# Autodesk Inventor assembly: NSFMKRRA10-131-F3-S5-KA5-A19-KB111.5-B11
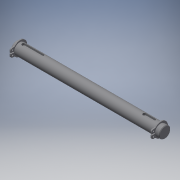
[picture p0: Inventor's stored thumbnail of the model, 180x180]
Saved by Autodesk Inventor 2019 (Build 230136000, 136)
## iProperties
Category: PARTsolutions
Company: MISUMI
Created: 2022-11
Part Number: NSFMKRRA10-131-F3-S5-KA5-A19-KB111.5-B11
Catalog Web Link: www.cadenas.de
Description: NSFMKRR, SFMKRR, PSFMKRR, SSFMKRR, NSFHKRR, SFHKRR, PSFHKRR, SSFHKRR, NSFGKRR, SFGKRR, PSFGKRR, SSFGKRR, NSFMKRRA, SFMKRRA, PSFMKRRA, SSFMKRRA, NSFHKRRA, SFHKRR
Vendor: MISUMI
Document SubType Name: Assembly
Designer: psAdmin
Manufacturer: MISUMI
Mass: 10.2368 g
Surface Area: 47.8895 cm^2
Volume: 10.2368 cm^3
Density: 1 g/cm^3
Title: NSFMKRRA10-131-F3-S5-KA5-A19-KB111.5-B11
Author: Cadenas PARTsolutions
Comments: Rotary Shafts - Retaining Ring Grooves on Both Ends with Keyway -
PSOL_IDENT_0: {$CADENAS_DATA/23d-libs/misumi/metric/11_rotary_shafts/psfgkrr_asmtab.prj},644 {VTYP=3D},{STYP=ASSTA
PSOL_IDENT_1: B},{NB=NSFMKRRA10-131-F3-S5-KA5-A19-KB111.5-B11},{LINA=NSFMKRRA10-131-F3-S5-KA5-A19-KB111.5-B11},{NN=
PSOL_IDENT_2: NSFMKRR, SFMKRR, PSFMKRR, SSFMKRR, NSFHKRR, SFHKRR, PSFHKRR, SSFHKRR, NSFGKRR, SFGKRR, PSFGKRR, SSFG
PSOL_IDENT_3: KRR, NSFMKRRA, SFMKRRA, PSFMKRRA, SSFMKRRA, NSFHKRRA, SFHKRRA, PSFHKRRA, SSFHKRRA, NSFGKRRA, SFGKRRA
PSOL_IDENT_4: , PSFGKRRA, SSFGKRRA},{DATE=25.01.2022 23:09:58},{GEOMDATE=05.02.2021 08:16:43},{VERSION=},{LINEID=3
PSOL_IDENT_5: 0},{WBVAR=TS,TYS,MAT,ST,ALT1,L,F,S,NOK,KA,A,KB,B,KC,C,ALT3,FC,GALT3,WFC,J,WALT3,V,ALT4,SFC,SG,AG,ALT
PSOL_IDENT_6: 10,KWC,ALT11,WC,ALT5,UC,ALT7,SC,ALT32,CD},{WBNUMERIC=L,F,S,KA,A,KB,B,KC,C,FC,GALT3,WFC,J,WALT3,V,SFC
PSOL_IDENT_7: ,SG,AG,KWC,WC,UC,SC}  {NB=NSFMKRRA10-131-F3-S5-KA5-A19-KB111.5-B11},{LINA=NSFMKRRA10-131-F3-S5-KA5-A
PSOL_IDENT_8: 19-KB111.5-B11},{KT=DUMMY},{PN=NSFMKRRA10-131-F3-S5-KA5-A19-KB111.5-B11},{TS=A},{TSALG='','Standard'
PSOL_IDENT_9: ,'A','Retaining Ring'},{TYS=M},{TYSALG= 'M','h9 (Cold-drawn)','H','h7 (Ground)','G','g6 (Ground)' },
PSOL_IDENT_10: {MAT=S45C},{MATALG= 'S45C','S45C Equivalent', 'SUS304','304 Stainless Steel' },{ST=},{STALG= '','-','
PSOL_IDENT_11: BO','Black Oxide', 'ENP','Electroless Nickel Plating' },{TYPE=NSFMKRR},{D=10},{ALT1=},{LKCMAX=799.9}
PSOL_IDENT_12: ,{L=131.0},{LALG=[15:800/0.1]},{LMIN=15},{LMAX=800},{F=3.0},{FALG=[3:126/0.1]},{FMIN=3},{FMAX1=122.8
PSOL_IDENT_13: },{FMIN2=6.2},{FMAX2=126},{S=5.0},{SALG=[3:126/0.1]},{SMIN1=3},{SMAX1=121},{SMIN2=6.2},{SMAX2=126},{
PSOL_IDENT_14: DD=9.6},{MM=1.15},{MMALG=1.2},{MMJ=2},{NOK=2},{NOKALG= '1', 'with 1 Key Groove', '2'  , 'with 2 Key
PSOL_IDENT_15: Grooves', '3'  , 'with 3 Key Grooves'},{CIFNOK1=0},{CIFNOK2=3},{CIFNOK3=0},{TOL1=0},{TOL2=3},{TOL3=0
PSOL_IDENT_16: },{BB=3},{TT=1.8},{KA=5.0},{KAALG=[5:116/0.1]},{KAMIN1=0},{KAMIN2=5},{KAMIN3=129.2},{KAMAX1=-1000},{
PSOL_IDENT_17: KAMAX2=116},{KAMAX3=-1000},{A=19.0},{AALG=[3:100/0.1]},{AMIN=3},{AMAX=100},{AMAX1=-1000},{AMAX2=100}
PSOL_IDENT_18: ,{AMAX3=-1000},{KAPN=-KA5-A19},{KB=111.5},{KBALG=[26:121/0.1]},{KBMIN1=26},{KBMIN2=26},{KBMIN3=129.2
PSOL_IDENT_19: },{KBMAX1=-1000},{KBMAX2=121},{KBMAX3=-1000},{B=11.0},{BALG=[3:12.5/0.1]},{BMIN=3},{BMAX=12.5},{BMAX
PSOL_IDENT_20: 1=-1000},{BMAX2=12.5},{BMAX3=-1000},{KBPN=-KB111.5-B11},{KC=0.0},{KCALG=[0]},{KCMIN1=124.5},{KCMIN2=
PSOL_IDENT_21: 124.5},{KCMIN3=129.2},{KCMAX1=-1000},{KCMAX2=-1000},{KCMAX3=-1000},{C=0.0},{CALG=0},{CMIN=3},{CMAX=-
PSOL_IDENT_22: 1000},{CMAX1=-1000},{CMAX2=-1000},{CMAX3=-1000},{CIFKA=5},{CIFKB=3},{CIFKC=3},{KCPN=},{ALT3=},{ALT3A
PSOL_IDENT_23: LG= '', 'w/o Set Screw Flat','FC','with FC (Adds a Set Screw Flat)','WFC','with WFC (Adds Two Set Sc
PSOL_IDENT_24: rew Flats)','FCWFC','with FC + WFC (Adds Three Set Screw Flats)' },{ALT3PN=},{FC=0},{FCALG=[0]},{FCM
PSOL_IDENT_25: IN=0},{FCMAX=130},{GALT3=0},{GALT3ALG=[0]},{GALT3MIN=1},{GALT3MAX=70},{GALT3MAX2=70},{GALT3MAX3=70},
PSOL_IDENT_26: {WFC=0},{WFCALG=[0]},{WFCMIN=0},{WFCMIN2=2},{WFCMAX=127},{WFCMAX2=-3},{WFCMAX3=-4},{J=0},{JALG=[0]},
PSOL_IDENT_27: {JMIN=1},{JMAX=70},{JMAX2=-2},{JMAX3=-5},{WALT3=0},{WALT3ALG=[0]},{WALT3MIN=0},{WALT3MIN2=133},{WALT
PSOL_IDENT_28: 3MAX=128},{WALT3MAX2=128},{V=0},{VALG=[0]},{VMIN=1},{VMAX=70},{VMAX2=70},{CIFFC=0},{ALT4=},{ALT4ALG=
PSOL_IDENT_29: '', 'w/o SFC (2 Set Screw Flats (Angle Specified))', 'SFC'  , 'with SFC (2 Set Screw Flats (Angle S
PSOL_IDENT_30: pecified))'},{ALT4PN=},{SFC=0},{SFCALG=[0]},{SFCMIN=0},{SFCMAX=130},{SG=0},{SGALG=[0]},{SGMIN=1},{SG
PSOL_IDENT_31: MAX=70},{AG=0},{AGALG=[0]},{H=0},{CIFSFC=0},{ALT10=},{ALT10ALG= '','Not applicable' },{KWC=0},{KWCAL
PSOL_IDENT_32: G=[0]},{KWCMIN=1},{KWCMAX=0},{WALT10=8},{ALT10PN=},{ALT11=},{ALT11ALG= '','Not applicable' },{WC=0.0
PSOL_IDENT_33: },{WCALG=[0]},{ALT11PN=},{ALT5=},{ALT5ALG= '', 'w/o UC (Slit Cam Groove)', 'UC', 'with UC (Slit Cam
PSOL_IDENT_34: Groove)'},{ALT5PN=},{UC=0},{UCALG=[0]},{UCMIN=1},{UCMAX=125},{DDALT5=0},{LL1=0},{ALT7=},{ALT7ALG= ''
PSOL_IDENT_35: , 'w/o SC (Wrench Flats)', 'SC', 'with SC (Wrench Flats)'},{ALT7PN=},{SC=0},{SCALG=[0]},{SCMIN=0},{S
PSOL_IDENT_36: CMAX=123},{LL2=0},{LL2ALG=8},{WALT7=0},{CIFSC=0},{ALT32=},{ALT32ALG= '','w/o CD (Changes Part D Cham
PSOL_IDENT_37: fering)','CD','with CD (Changes Part D Chamfering)' },{CD=},{CDALG= '','N/A' },{CD3D=0.5},{ALT32PN=}
PSOL_IDENT_38: ,{CIF323R=0},{CIF323L=0},{CIF324R=0},{CIF324L=0},{CIF3210=0},{CIF32F=0},{CIF32S=0},{ERRORPN=},{ERROR
PSOL_IDENT_39: KGALT3=OK},{ERRORKGALT4=OK},{ERRORKGALT5=OK},{ERRORKGALT7=OK},{ERRORKGALT10=OK},{ERRORRALT3=OK},{ERR
PSOL_IDENT_40: ORRALT4=NG},{ERRORRALT5=NG},{ERRORRALT7=NG},{ERRORRALT10=OK},{ERRORALT34=OK},{ERRORALT35=OK},{ERRORA
PSOL_IDENT_41: LT37=OK},{ERRORALT310=OK},{ERRORALT45=OK},{ERRORALT47=OK},{ERRORALT410=OK},{ERRORALT57=OK},{ERRORALT
PSOL_IDENT_42: 510=OK},{ERRORALT710=OK},{PCUT3D=0},{QCUT3D=0},{TTALT2=1.8},{BBALT2=3},{PPATH=11_components/psfgkrr/
PSOL_IDENT_43: psfgkrr_asmtpl.prj}
NB: NSFMKRRA10-131-F3-S5-KA5-A19-KB111.5-B11
NN: NSFMKRR, SFMKRR, PSFMKRR, SSFMKRR, NSFHKRR, SFHKRR, PSFHKRR, SSFHKRR, NSFGKRR, SFGKRR, PSFGKRR, SSFGKRR, NSFMKRRA, SFMKRRA, PSFMKRRA, SSFMKRRA, NSFHKRRA, SFHKRR
NT: Rotary Shafts - Retaining Ring Grooves on Both Ends with Keyway -
NBSYN: $PN.
LINA: NSFMKRRA10-131-F3-S5-KA5-A19-KB111.5-B11
CATALOG: Misumi
PN: NSFMKRRA10-131-F3-S5-KA5-A19-KB111.5-B11
TS: Retaining Ring
TYS: h9 (Cold-drawn)
MAT: S45C Equivalent
ST: -
D: 10
ALT1: w/o LKC (Changes L Tolerance)
L: 131
F: 3
S: 5
DD: 9.6
MM: 1.15
NOK: with 2 Key Grooves
KA: 5
A: 19
KB: 111.5
B: 11
KC: 0
C: 0
ALT3: w/o Set Screw Flat
FC: 0
GALT3: 0
WFC: 0
J: 0
WALT3: 0
V: 0
ALT4: w/o SFC (2 Set Screw Flats (Angle Specified))
SFC: 0
SG: 0
AG: 0
H: 0
ALT10: Not applicable
KWC: 0
ALT11: Not applicable
WC: 0
ALT5: w/o UC (Slit Cam Groove)
UC: 0
DDALT5: 0
LL1: 0
ALT7: w/o SC (Wrench Flats)
SC: 0
LL2: 0
WALT7: 0
ALT32: w/o CD (Changes Part D Chamfering)
CD: N/A
SUPPLIER: MISUMI
ARTICLENO: NSFMKRRA10-131-F3-S5-KA5-A19-KB111.5-B11
BOMINFO: NSFMKRRA10-131-F3-S5-KA5-A19-KB111.5-B11
CREATOR: CADENAS GmbH
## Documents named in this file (3)
- e:\temp\worker_COMMON_4\temp\tmp_3352_176_HThwi\format_0\NSFMKRRA10-131-F3-S5-KA5-A19-KB111_5-B11.iam
- e:\temp\worker_COMMON_4\temp\tmp_3352_176_HThwi\format_0\NSFMKRRA10-131-F3-S5-KA5-A19-KB111_5-B11_s.ipt
- e:\temp\worker_COMMON_4\temp\tmp_3352_176_HThwi\format_0\STWS10.ipt
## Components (3 placed, 2 different names)
1. NSFMKRRA10-131-F3-S5-KA5-A19-KB111_5-B11_s:1 — to_rring_1_XY@1 <-> 1_XY@2, to_rring_1_Z@1 <-> 1_Z@2, to_rring_1_YZ@1 <-> 1_YZ@2, to_rring_2_XY@1 <-> 1_XY@3, to_rring_2_Z@1 <-> 1_Z@3, to_rring_2_YZ@1 <-> 1_YZ@3
2. STWS10:1 — to_rring_1_XY@1 <-> 1_XY@2, to_rring_1_Z@1 <-> 1_Z@2, to_rring_1_YZ@1 <-> 1_YZ@2
3. STWS10:2 — to_rring_2_XY@1 <-> 1_XY@3, to_rring_2_Z@1 <-> 1_Z@3, to_rring_2_YZ@1 <-> 1_YZ@3
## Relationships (6: Mate 4, Angle 2)
- to_rring_1_XY@1 <-> 1_XY@2 [Mate]: NSFMKRRA10-131-F3-S5-KA5-A19-KB111_5-B11_s:1 ↔ STWS10:1
- to_rring_1_Z@1 <-> 1_Z@2 [Mate]: NSFMKRRA10-131-F3-S5-KA5-A19-KB111_5-B11_s:1 ↔ STWS10:1
- to_rring_1_YZ@1 <-> 1_YZ@2 [Angle]: NSFMKRRA10-131-F3-S5-KA5-A19-KB111_5-B11_s:1 ↔ STWS10:1
- to_rring_2_XY@1 <-> 1_XY@3 [Mate]: NSFMKRRA10-131-F3-S5-KA5-A19-KB111_5-B11_s:1 ↔ STWS10:2
- to_rring_2_Z@1 <-> 1_Z@3 [Mate]: NSFMKRRA10-131-F3-S5-KA5-A19-KB111_5-B11_s:1 ↔ STWS10:2
- to_rring_2_YZ@1 <-> 1_YZ@3 [Angle]: NSFMKRRA10-131-F3-S5-KA5-A19-KB111_5-B11_s:1 ↔ STWS10:2
